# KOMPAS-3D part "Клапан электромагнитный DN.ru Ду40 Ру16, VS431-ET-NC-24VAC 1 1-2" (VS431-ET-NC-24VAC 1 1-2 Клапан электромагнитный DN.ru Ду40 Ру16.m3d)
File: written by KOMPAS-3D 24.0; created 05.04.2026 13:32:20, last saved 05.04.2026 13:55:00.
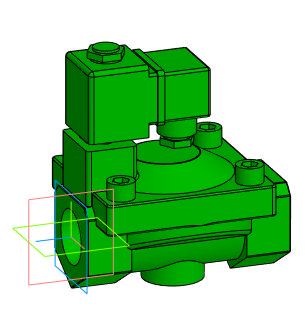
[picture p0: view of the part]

Document properties: Автор: artio; Полное имя файла: C:\Users\artio\OneDrive\Рабочий стол\Клапан электромагнитный DN.ru\VS431\VS431-ET-NC\VS431-ET-NC-24VAC\Ду40\VS431-ET-NC-24VAC 1 1-2 Клапан электромагнитный DN.ru Ду40 Ру16.m3d

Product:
- Body: Тело 1  | qty 1
    Масса: 3.859459
- Part/product: Клапан электромагнитный DN.ru Ду40 Ру16  | designation VS431-ET-NC-24VAC 1 1-2
    Масса: 2.285
    Раздел спецификации: Прочие изделия
    Примечание: D130-05506
    additional columns: ef56311e-7521-43dc-8291-0e6108b3d81d; artio; c; Шероховатость не задана; Да

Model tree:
1. Операция без истории:1

Expressions: VS431-ET-NC-24VAC 1 1-2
